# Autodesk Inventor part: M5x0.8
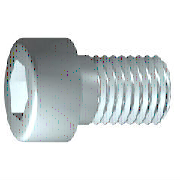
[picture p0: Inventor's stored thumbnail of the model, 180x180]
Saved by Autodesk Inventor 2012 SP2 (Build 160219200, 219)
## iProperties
IsCustomPart: 0
Manager: KYOUNG IL JANG
Company: 한국ATC센터
Created: 2009-02
Part Number: M5x0.8
Material: Steel, Mild
Description: 6각머리 태핑 나사
Document SubType Name: Modeling
Standard: KS B 1003
Standards Organization: KS
Language: ko-KR
Size Designation: M 5 x 20
Categories: <MemberInstance><Categories><Category DisplayName="조임쇠" InternalName="e4da775c-781d-43d5-af7c-5136215cf5a6" Mnemonic="FSTN"><Category DisplayName="볼트" InternalN
Density: 1 g/cm^3
Checked By: KYOUNG IL JANG
Vendor: CBT Solutions
Designer: KYOUNG IL JANG
Author: KYOUNG IL JANG
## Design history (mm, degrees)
body "Solid1"
workplane "Work Plane1"
fillet "Fillet2" dims "d30" = 0.1 (= R)
revolve "본체" stored, may be unused: angle "d10" = 90 deg
sketch "스케치2"
  geometry: L1 (0, -5.95)-(0, 5.95) reference; L2 (-5.95, 0)-(5.95, 0) reference; L3 (2.309, 0)-(1.155, -2); L4 (1.155, -2)-(-1.155, -2); L5 (-1.155, -2)-(-2.309, 0); L6 (-2.309, 0)-(-1.155, 2); L7 (-1.155, 2)-(1.155, 2); L8 (1.155, 2)-(2.309, 0); 2 further points
  constraints: 12 end point, 1 coincident, 1 horizontal alignment, 1 point on line, 12 other
extrude "슬롯" join sketch "스케치2" stored distance "d11" = 10; taper "d12" = 0 deg
fillet "모깎기1" dims "d17" = 0.5 (= RR)
feature "스레드" dims "d13" = 18 (= GEL), "d14" = 0
chamfer "모따기1" distance "d15" = 0.49076 (= -0.5 x SPD + 0.5 x GD); stored, may be unused: second distance "d16" = 0.49076 (= GUL), angle "d27" = 45 deg
sketch "스케치1"
  geometry: L1 (-1.167, 0)-(20, 0); L2 (20, 0)-(20, 2.5); L3 (20, 2.5)-(2, 2.5); L4 (2, 2.5)-(1.509, 2.5); L5 (1.509, 2.5)-(0, 2.5); L6 (0, 2.5)-(0, 4.25); L7 (0, 4.25)-(-5, 4.25); L8 (-5, 4.25)-(-5, 2.309); L9 (-5, 2.309)-(-2.5, 2.309); L10 (-2.5, 2.309)-(-1.167, 0); L11 (-10, 0)-(25, 0) reference; L12 (0, -0.85)-(0, 5.1) reference; L13 (2, 2.5)-(0, 2.5)
  constraints: 22 end point, 6 parallel, 2 collinear, 2 perpendicular, 1 horizontal, 1 point on line
  dimensions: "d1" = 18 distance from line of L3.end L2 (= GEL); "d2" = 0.49086 distance of L4.end L3.end (computed from GAL); "d3" = 5 distance between parallel lines of L8 L6 (= KOH); "d4" = 2.5 distance of L8.end L9.end (= INTI); "d5" = 60 deg angle of L10 L1; "d6" = 5 diameter of L3 L1 (= GD); "d7" = 5 diameter of L5 L1 (= BDM); "d8" = 4.6188 diameter of L9 L1 (= 1.1547 x SW); "d9" = 8.5 diameter of L7 L1 (= KOD); "d26" = 20 distance between parallel lines of L12 L2 (= NLG)
other parameters: "GD" = 5 (= NND) [user parameter; used in 2 equation terms], "NLG" = 20 [user parameter; used in 1 equation term], "GEL" = 18 [user parameter; used in 2 equation terms], "KOD" = 8.5 [user parameter; used in 1 equation term], "KOH" = 5 [user parameter; used in 1 equation term], "INTI" = 2.5 [user parameter; used in 1 equation term], "GAL" = 0.49076 (= 0.61345 x PTC) [user parameter; used in 1 equation term], "GUL" = 0.49076 (= 0.61345 x PTC) [user parameter; used in 1 equation term], "BDM" = 5 (= NND) [user parameter; used in 1 equation term], "SW" = 4 [user parameter; used in 2 equation terms], "RR" = 0.5 [user parameter; used in 1 equation term], "SPD" = 4.01848 (= NND - 1.2269 x PTC) [user parameter; used in 1 equation term], "d19" = 0, "d28" = 0, "d29" = 0, "R" = 0.1 [user parameter; used in 1 equation term], "PHH" = 0.2 [user parameter], "GD1" = 4.01848 (= THREADDIA - 1.2269 x PTC) [user parameter], "THREADDIA" = 5 [user parameter; used in 1 equation term], "FAWI" = 45 deg [user parameter], "TPU" = 12.5 (computed from PTC) [user parameter], "PTC" = 0.8 [user parameter; used in 5 equation terms], "NND" = 5 [user parameter; used in 3 equation terms], "TOA" = 30 deg [user parameter], "E0" = 4.62 (= 1.155 x SW) [user parameter]
